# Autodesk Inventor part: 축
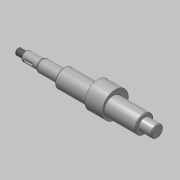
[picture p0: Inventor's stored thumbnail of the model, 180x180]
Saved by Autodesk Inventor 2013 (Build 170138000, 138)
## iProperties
Created: 2015-12
Part Number: 축
Document SubType Name: Modeling
Designer: mdu
Density: 7.86 g/cm^3
Material: 강철, 연강
Author: mdu
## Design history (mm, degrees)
sketch "스케치1"
  geometry: L1 (62, 100.9)-(62, 67.1) reference; L2 (51, 101.2)-(51, 84) reference; L3 (-51, 84)-(-51, 101.2) reference; L4 (-62, 67.1)-(-62, 100.9) reference; L5 (-51.6, 91.5)-(-61.4, 91.5) reference; L6 (51.6, 91.5)-(61.4, 91.5) reference; L7 (67, 84)-(-109, 84); L8 (-77, 64.201)-(-77, 103.799) reference; L9 (67, 84)-(67, 91.5); L10 (67, 91.5)-(51, 91.5); L11 (51, 91.5)-(51, 95.5); L12 (51, 95.5)-(-51, 95.5); L13 (-51, 95.5)-(-51, 91.5); L14 (-51, 91.5)-(-79, 91.5); L15 (-79, 91.5)-(-79, 90); L16 (-79, 90)-(-99, 90); L17 (-99, 90)-(-99, 88); L18 (-99, 88)-(-109, 88); L19 (-109, 88)-(-109, 84); 2 further points
  constraints: 28 end point, 7 parallel, 5 point on line, 4 perpendicular, 2 collinear, 2 horizontal, 1 midpoint, 4 other
  dimensions: "d0" = 5 distance from line of L7.start L1; "d2" = 2 distance between parallel lines of L15 L8; "d3" = 23 diameter of L12 L7; "d4" = 12 diameter of L16 L7; "d7" = 20 distance of L15.end L16.end; "d8" = 10 distance between parallel lines of L17 L19; "d9" = 8 diameter of L18 L7
revolve "회전1" sketch "스케치1" stored, may be unused: angle "d10" = 90 deg
sketch "스케치2"
  geometry: C1 r 11.5 at (84, 0) reference; C2 r 11.5 at (84, 0) reference; C3 r 16.5 at (87, 0); 1 further point
  constraints: 1 centre point, 1 horizontal alignment
  dimensions: "d11" = 33 diameter of C3; "d12" = 3 distance of C3.centre C1.centre
extrude "돌출1" join sketch "스케치2" stored distance "d13" = 22; taper "d14" = 0 deg
chamfer "모따기1" distance "d15" = 1; stored, may be unused: second distance "d16" = 2, angle "d17" = 45 deg
feature "스레드1" dims "d18" = 8, "d19" = 0
node "작업 평면1"
sketch "스케치3"
  geometry: L1 (-5, -2)-(3, -2); L2 (3, 2)-(-5, 2); L3 (-10, -5)-(-10, 5) reference; A1 r 2 centre (3, 0) between (3, -2) and (3, 2); A2 r 2 centre (-5, 0) between (-5, 2) and (-5, -2); 2 further points
  constraints: 4 end point, 4 point on circle, 4 tangent, 2 centre point, 1 horizontal, 1 horizontal alignment, 1 midpoint, 1 parallel
  dimensions: "d20" = 4 distance between parallel lines of L1 L2; "d21" = 12 dimension on A1 A2; "d22" = 3 distance edge to line of A2 L3
extrude "돌출2" cut sketch "스케치3" distance "d23" = 2.5; taper "d24" = 0 deg
fillet "모깎기1" dims "d25" = 0.3
chamfer "모따기2" distance "d27" = 1.65; stored, may be unused: second distance "d28" = 2, angle "d29" = 30 deg
fillet "모깎기3" dims "d30" = 2
node "솔리드1"
node "참조1"
node "참조2"
node "참조3"
node "참조4"
node "참조5"
node "투영된 루프1"
